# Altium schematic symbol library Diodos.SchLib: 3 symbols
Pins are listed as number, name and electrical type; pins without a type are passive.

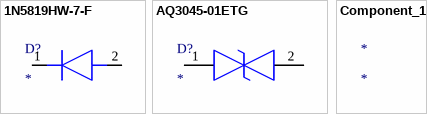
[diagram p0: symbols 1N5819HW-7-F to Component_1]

## 1N5819HW-7-F
designator D?
Diode; Manufacturer_Name: Multicomp Pro; Manufacturer_Part_Number: 1N5819HW-7-F
footprint SOD3716X125N
pins: 1 K, 2 A

## AQ3045-01ETG
designator D?
TVS Diode (Bi-directional); Manufacturer_Name: LITTELFUSE; Manufacturer_Part_Number: AQ3045-01ETG
footprint AQ304501ETG
pins: 1, 2

## Component_1
designator *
